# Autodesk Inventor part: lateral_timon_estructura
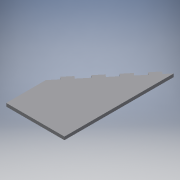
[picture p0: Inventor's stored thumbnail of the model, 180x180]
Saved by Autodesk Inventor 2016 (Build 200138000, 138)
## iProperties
Created: 2017-06
Part Number: lateral_timon_estructura
Material: Generic
Document SubType Name: Modeling
Designer: laboratorioesan
Density: 1 g/cm^3
Appearance: Default
Author: laboratorioesan
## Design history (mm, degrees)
sketch "Sketch1"
  geometry: L1 (0, 0)-(32.036, 38.389) reference; L2 (0, 0)-(11.901, -9.931) reference; L3 (43.937, 28.458)-(11.901, -9.931) reference; L4 (32.036, 38.389)-(43.937, 28.458) reference; L5 (-64.072, -76.777)-(-32.036, -38.389) reference; L6 (-64.072, -76.777)-(-52.172, -86.709) reference; L7 (-20.136, -48.32)-(-52.172, -86.709) reference; L8 (-32.036, -38.389)-(-20.136, -48.32) reference; L9 (-128.144, -153.555)-(-96.108, -115.166) reference; L10 (-128.144, -153.555)-(-116.244, -163.486) reference; L11 (-84.208, -125.097)-(-116.244, -163.486) reference; L12 (-96.108, -115.166)-(-84.208, -125.097) reference; L13 (-198.623, -238.01)-(-166.587, -199.621) reference; L14 (-198.623, -238.01)-(-186.723, -247.941) reference; L15 (-154.687, -209.552)-(-186.723, -247.941) reference; L16 (-166.587, -199.621)-(-154.687, -209.552) reference; L17 (-0.435, -485.534)-(49.565, -485.534) reference; L18 (-0.435, -485.534)-(-0.435, -501.034) reference; L19 (49.565, -501.034)-(-0.435, -501.034) reference; L20 (49.565, -485.534)-(49.565, -501.034) reference; L21 (-100.435, -485.534)-(-50.435, -485.534) reference; L22 (-100.435, -485.534)-(-100.435, -501.034) reference; L23 (-50.435, -501.034)-(-100.435, -501.034) reference; L24 (-50.435, -485.534)-(-50.435, -501.034) reference; L25 (-200.44, -485.534)-(-150.44, -485.534) reference; L26 (-200.44, -485.534)-(-200.44, -501.034) reference; L27 (-150.44, -501.034)-(-200.44, -501.034) reference; L28 (-150.44, -485.534)-(-150.44, -501.034) reference; L29 (-220.44, -485.534)-(69.565, -485.534); L30 (69.565, -485.534)-(69.565, 59.169); L31 (69.565, 59.169)-(-220.44, -288.345); L32 (-220.44, -288.345)-(-220.44, -485.534)
  constraints: 8 end point, 1 collinear, 1 horizontal, 1 parallel, 1 perpendicular, 1 point on line
  dimensions: "d0" = 20 distance of L25.start L29.start; "d1" = 20 distance of L29.end L17.end
extrude "Extrusion1" new body sketch "Sketch1" distance "d2" = 15.5; taper "d3" = 0 deg
body "Solid1"
node "Reference1"
node "Reference2"
node "Reference3"
node "Reference4"
node "Reference5"
node "Reference6"
node "Reference7"
node "Reference8"
